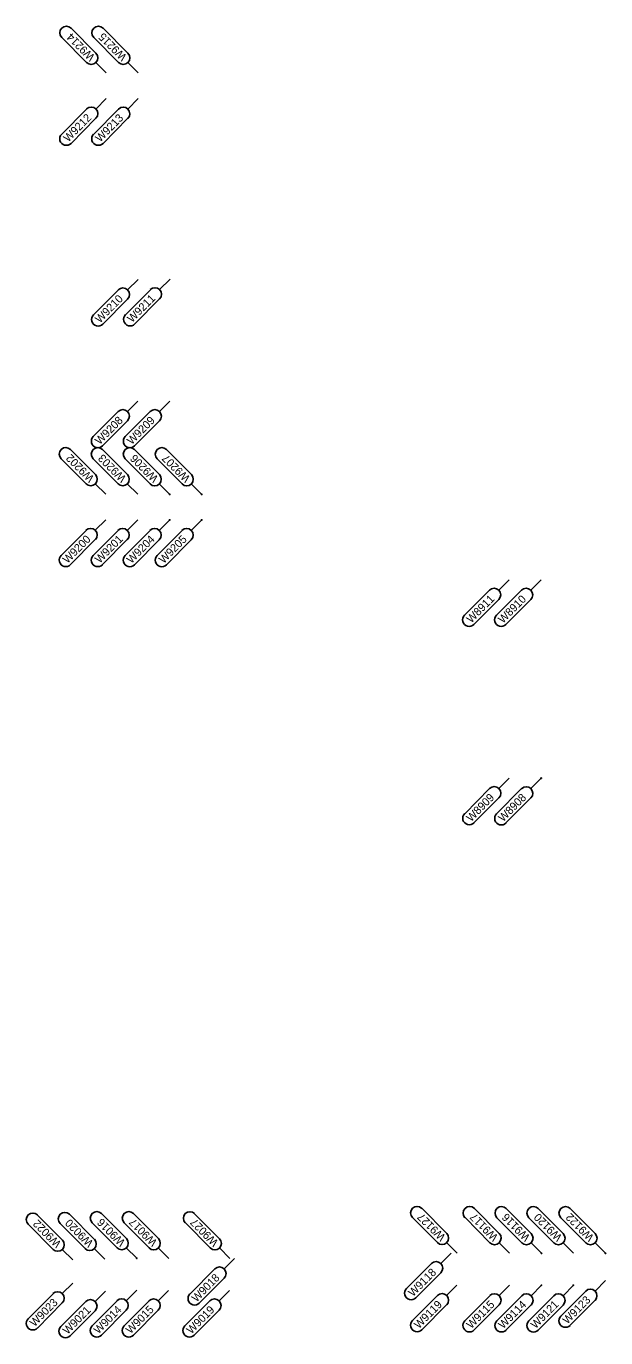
# Model space of a CAD drawing. Extents: x 12479652 to 12487250, y 9842710 to 9846560.
# Drawn here: x 12483659.7 to 12483750.3, y 9843890.4 to 9844095.3 of the extents above; entities that cross this region are included whole.
import ezdxf

# ---------------------------------------------------------------- set-up
doc = ezdxf.new("R2010")
doc.units = 0
for name, color, linetype in [('_CIVIL_CONSTRUCTION', 7, 'Continuous'), ('Default', 7, 'Continuous'), ('TextAlignmentLrg', 7, 'Continuous')]:
    doc.layers.add(name, color=color, linetype=linetype)

msp = doc.modelspace()

# ---------------------------------------------------------------- linework, layer by layer
at = {"layer": '_CIVIL_CONSTRUCTION'}
for p, q in [((12483735.18, 9844008.84), (12483733.56, 9844007.21)), ((12483740.18, 9844008.83), (12483738.56, 9844007.2)), ((12483728.22, 9844003.29), (12483732.11, 9844007.2)), ((12483733.22, 9844003.28), (12483737.11, 9844007.2)), ((12483733.57, 9844005.76), (12483729.68, 9844001.85)), ((12483738.57, 9844005.75), (12483734.68, 9844001.84)), ((12483735.2, 9843977.84), (12483733.58, 9843976.21)), ((12483740.2, 9843977.83), (12483738.58, 9843976.2)), ((12483728.24, 9843972.29), (12483732.13, 9843976.2)), ((12483733.24, 9843972.28), (12483737.13, 9843976.2)), ((12483733.58, 9843974.76), (12483729.69, 9843970.84)), ((12483738.58, 9843974.75), (12483734.69, 9843970.84))]:
    msp.add_line(p, q, dxfattribs=at)
for centre, start, end in [((12483732.84, 9844006.48), 315.1702, 135.1702), ((12483737.84, 9844006.47), 315.1702, 135.1702), ((12483728.95, 9844002.57), 135.1702, 315.1702), ((12483733.95, 9844002.56), 135.1702, 315.1702), ((12483732.86, 9843975.48), 315.1702, 135.1702), ((12483737.86, 9843975.47), 315.1702, 135.1702), ((12483728.97, 9843971.57), 135.1702, 315.1702), ((12483733.97, 9843971.56), 135.1702, 315.1702)]:
    msp.add_arc(centre, 1.03, start, end, dxfattribs=at)
at = {"layer": 'Default'}
for p, q in [((12483670.61, 9844091.09), (12483666.72, 9844095)), ((12483675.61, 9844091.08), (12483671.72, 9844094.99)), ((12483665.27, 9844093.56), (12483669.16, 9844089.64)), ((12483670.27, 9844093.55), (12483674.16, 9844089.63)), ((12483672.23, 9844088.01), (12483670.61, 9844089.64)), ((12483677.23, 9844088), (12483675.61, 9844089.63)), ((12483665.26, 9844078.46), (12483669.15, 9844082.37)), ((12483670.26, 9844078.45), (12483674.15, 9844082.36)), ((12483672.23, 9844084.01), (12483670.6, 9844082.37)), ((12483677.23, 9844084), (12483675.6, 9844082.37)), ((12483670.61, 9844080.92), (12483666.72, 9844077.01)), ((12483675.61, 9844080.92), (12483671.72, 9844077)), ((12483677.19, 9844055.75), (12483675.57, 9844054.12)), ((12483682.19, 9844055.79), (12483680.57, 9844054.16)), ((12483670.23, 9844050.2), (12483674.12, 9844054.12)), ((12483675.23, 9844050.24), (12483679.12, 9844054.15)), ((12483675.57, 9844052.67), (12483671.68, 9844048.76)), ((12483680.57, 9844052.71), (12483676.68, 9844048.79)), ((12483677.16, 9844036.75), (12483675.54, 9844035.12)), ((12483682.16, 9844036.74), (12483680.54, 9844035.11)), ((12483670.2, 9844031.2), (12483674.09, 9844035.12)), ((12483675.55, 9844033.67), (12483671.66, 9844029.76)), ((12483675.2, 9844031.19), (12483679.09, 9844035.11)), ((12483680.55, 9844033.66), (12483676.66, 9844029.75)), ((12483670.53, 9844025.27), (12483666.64, 9844029.18)), ((12483675.53, 9844025.26), (12483671.64, 9844029.18)), ((12483680.53, 9844025.26), (12483676.64, 9844029.17)), ((12483685.53, 9844025.25), (12483681.64, 9844029.16)), ((12483665.18, 9844027.74), (12483669.07, 9844023.82)), ((12483670.18, 9844027.73), (12483674.07, 9844023.82)), ((12483675.18, 9844027.72), (12483679.07, 9844023.81)), ((12483680.18, 9844027.72), (12483684.07, 9844023.8)), ((12483672.14, 9844022.19), (12483670.52, 9844023.82)), ((12483677.14, 9844022.18), (12483675.52, 9844023.81)), ((12483682.14, 9844022.17), (12483680.52, 9844023.81)), ((12483687.14, 9844022.17), (12483685.52, 9844023.8)), ((12483672.14, 9844018.19), (12483670.52, 9844016.56)), ((12483677.14, 9844018.18), (12483675.52, 9844016.55)), ((12483682.14, 9844018.17), (12483680.52, 9844016.54)), ((12483687.14, 9844018.17), (12483685.52, 9844016.54)), ((12483665.18, 9844012.64), (12483669.07, 9844016.55)), ((12483670.52, 9844015.11), (12483666.63, 9844011.19)), ((12483670.18, 9844012.63), (12483674.07, 9844016.55)), ((12483675.52, 9844015.1), (12483671.63, 9844011.19)), ((12483675.18, 9844012.63), (12483679.07, 9844016.54)), ((12483680.52, 9844015.09), (12483676.63, 9844011.18)), ((12483680.18, 9844012.62), (12483684.07, 9844016.53)), ((12483685.52, 9844015.09), (12483681.63, 9844011.17)), ((12483725.43, 9843906.73), (12483721.54, 9843910.64)), ((12483733.64, 9843906.71), (12483729.75, 9843910.63)), ((12483738.63, 9843906.71), (12483734.74, 9843910.62)), ((12483743.63, 9843906.7), (12483739.74, 9843910.61)), ((12483748.63, 9843906.69), (12483744.74, 9843910.6)), ((12483660.02, 9843908.14), (12483663.91, 9843904.23)), ((12483665.37, 9843905.68), (12483661.48, 9843909.59)), ((12483665.02, 9843908.26), (12483668.91, 9843904.35)), ((12483670.37, 9843905.79), (12483666.48, 9843909.71)), ((12483670.02, 9843908.38), (12483673.91, 9843904.47)), ((12483675.37, 9843905.91), (12483671.48, 9843909.83)), ((12483675.02, 9843908.37), (12483678.91, 9843904.46)), ((12483680.37, 9843905.91), (12483676.48, 9843909.82)), ((12483684.59, 9843908.36), (12483688.48, 9843904.44)), ((12483689.93, 9843905.89), (12483686.04, 9843909.8)), ((12483720.09, 9843909.19), (12483723.98, 9843905.28)), ((12483728.3, 9843909.18), (12483732.19, 9843905.27)), ((12483733.28, 9843909.17), (12483737.17, 9843905.26)), ((12483738.28, 9843909.16), (12483742.17, 9843905.25)), ((12483743.28, 9843909.16), (12483747.17, 9843905.24)), ((12483666.99, 9843902.59), (12483665.36, 9843904.22)), ((12483671.99, 9843902.71), (12483670.36, 9843904.34)), ((12483676.99, 9843902.83), (12483675.36, 9843904.46)), ((12483681.99, 9843902.82), (12483680.36, 9843904.45)), ((12483691.55, 9843902.81), (12483689.93, 9843904.44)), ((12483727.05, 9843903.64), (12483725.43, 9843905.27)), ((12483735.26, 9843903.63), (12483733.64, 9843905.26)), ((12483740.24, 9843903.62), (12483738.62, 9843905.25)), ((12483745.24, 9843903.62), (12483743.62, 9843905.25)), ((12483750.24, 9843903.61), (12483748.62, 9843905.24)), ((12483692.28, 9843902.81), (12483690.66, 9843901.18)), ((12483719.17, 9843898.1), (12483723.06, 9843902.01)), ((12483726.13, 9843903.64), (12483724.51, 9843902.01)), ((12483685.32, 9843897.26), (12483689.21, 9843901.17)), ((12483724.51, 9843900.56), (12483720.62, 9843896.65)), ((12483666.98, 9843898.94), (12483665.36, 9843897.31)), ((12483690.66, 9843899.73), (12483686.77, 9843895.81)), ((12483727.04, 9843898.64), (12483725.42, 9843897.01)), ((12483735.23, 9843898.63), (12483733.61, 9843897)), ((12483740.23, 9843898.62), (12483738.61, 9843896.99)), ((12483745.23, 9843898.62), (12483743.61, 9843896.98)), ((12483750.24, 9843899.35), (12483748.61, 9843897.72)), ((12483660.02, 9843893.39), (12483663.91, 9843897.3)), ((12483665.36, 9843895.86), (12483661.47, 9843891.94)), ((12483665.14, 9843892.17), (12483669.03, 9843896.08)), ((12483670.02, 9843892.28), (12483673.91, 9843896.2)), ((12483672.1, 9843897.71), (12483670.48, 9843896.08)), ((12483675.02, 9843892.27), (12483678.91, 9843896.19)), ((12483676.98, 9843897.83), (12483675.36, 9843896.2)), ((12483681.98, 9843897.82), (12483680.36, 9843896.19)), ((12483684.52, 9843892.26), (12483688.41, 9843896.17)), ((12483691.49, 9843897.81), (12483689.86, 9843896.18)), ((12483720.08, 9843893.09), (12483723.97, 9843897.01)), ((12483728.27, 9843893.08), (12483732.16, 9843896.99)), ((12483733.27, 9843893.07), (12483737.16, 9843896.99)), ((12483738.27, 9843893.07), (12483742.16, 9843896.98)), ((12483743.27, 9843893.8), (12483747.16, 9843897.72)), ((12483748.62, 9843896.27), (12483744.73, 9843892.36)), ((12483670.49, 9843894.63), (12483666.6, 9843890.72)), ((12483675.36, 9843894.75), (12483671.47, 9843890.84)), ((12483680.36, 9843894.74), (12483676.47, 9843890.83)), ((12483689.87, 9843894.73), (12483685.98, 9843890.81)), ((12483725.42, 9843895.56), (12483721.53, 9843891.65)), ((12483733.62, 9843895.55), (12483729.73, 9843891.64)), ((12483738.62, 9843895.54), (12483734.73, 9843891.63)), ((12483743.62, 9843895.53), (12483739.73, 9843891.62))]:
    msp.add_line(p, q, dxfattribs=at)
for centre, start, end in [((12483666, 9844094.28), 44.8253, 224.8253), ((12483671, 9844094.27), 44.8253, 224.8253), ((12483669.89, 9844090.37), 224.8253, 44.8253), ((12483674.89, 9844090.36), 224.8253, 44.8253), ((12483669.88, 9844081.65), 315.1702, 135.1702), ((12483674.88, 9844081.64), 315.1702, 135.1702), ((12483665.99, 9844077.73), 135.1702, 315.1702), ((12483670.99, 9844077.73), 135.1702, 315.1702), ((12483674.84, 9844053.39), 315.1702, 135.1702), ((12483679.84, 9844053.43), 315.1702, 135.1702), ((12483670.95, 9844049.48), 135.1702, 315.1702), ((12483675.95, 9844049.52), 135.1702, 315.1702), ((12483674.82, 9844034.39), 315.1702, 135.1702), ((12483679.82, 9844034.38), 315.1702, 135.1702), ((12483670.93, 9844030.48), 135.1702, 315.1702), ((12483675.93, 9844030.47), 135.1702, 315.1702), ((12483665.91, 9844028.46), 44.8253, 224.8253), ((12483670.91, 9844028.45), 44.8253, 224.8253), ((12483675.91, 9844028.45), 44.8253, 224.8253), ((12483680.91, 9844028.44), 44.8253, 224.8253), ((12483669.8, 9844024.55), 224.8253, 44.8253), ((12483674.8, 9844024.54), 224.8253, 44.8253), ((12483679.8, 9844024.53), 224.8253, 44.8253), ((12483684.8, 9844024.53), 224.8253, 44.8253), ((12483669.79, 9844015.83), 315.1702, 135.1702), ((12483674.79, 9844015.82), 315.1702, 135.1702), ((12483679.79, 9844015.82), 315.1702, 135.1702), ((12483684.79, 9844015.81), 315.1702, 135.1702), ((12483665.9, 9844011.92), 135.1702, 315.1702), ((12483670.9, 9844011.91), 135.1702, 315.1702), ((12483675.9, 9844011.9), 135.1702, 315.1702), ((12483680.9, 9844011.9), 135.1702, 315.1702), ((12483720.81, 9843909.91), 44.8253, 224.8253), ((12483729.02, 9843909.9), 44.8253, 224.8253), ((12483734.01, 9843909.89), 44.8253, 224.8253), ((12483739.01, 9843909.89), 44.8253, 224.8253), ((12483744.01, 9843909.88), 44.8253, 224.8253), ((12483660.75, 9843908.87), 44.8253, 224.8253), ((12483665.75, 9843908.98), 44.8253, 224.8253), ((12483670.75, 9843909.1), 44.8253, 224.8253), ((12483675.75, 9843909.1), 44.8253, 224.8253), ((12483685.31, 9843909.08), 44.8253, 224.8253), ((12483724.7, 9843906), 224.8253, 44.8253), ((12483732.91, 9843905.99), 224.8253, 44.8253), ((12483737.9, 9843905.98), 224.8253, 44.8253), ((12483742.9, 9843905.97), 224.8253, 44.8253), ((12483747.9, 9843905.97), 224.8253, 44.8253), ((12483664.64, 9843904.95), 224.8253, 44.8253), ((12483669.64, 9843905.07), 224.8253, 44.8253), ((12483674.64, 9843905.19), 224.8253, 44.8253), ((12483679.64, 9843905.18), 224.8253, 44.8253), ((12483689.2, 9843905.17), 224.8253, 44.8253), ((12483723.78, 9843901.29), 315.1702, 135.1702), ((12483689.93, 9843900.45), 315.1702, 135.1702), ((12483719.89, 9843897.37), 135.1702, 315.1702), ((12483747.89, 9843896.99), 315.1702, 135.1702), ((12483664.63, 9843896.58), 315.1702, 135.1702), ((12483669.76, 9843895.35), 315.1702, 135.1702), ((12483674.63, 9843895.47), 315.1702, 135.1702), ((12483679.63, 9843895.46), 315.1702, 135.1702), ((12483686.04, 9843896.54), 135.1702, 315.1702), ((12483689.14, 9843895.45), 315.1702, 135.1702), ((12483724.7, 9843896.28), 315.1702, 135.1702), ((12483732.89, 9843896.27), 315.1702, 135.1702), ((12483737.89, 9843896.26), 315.1702, 135.1702), ((12483742.89, 9843896.26), 315.1702, 135.1702), ((12483744, 9843893.08), 135.1702, 315.1702), ((12483660.75, 9843892.67), 135.1702, 315.1702), ((12483665.87, 9843891.44), 135.1702, 315.1702), ((12483670.74, 9843891.56), 135.1702, 315.1702), ((12483675.74, 9843891.55), 135.1702, 315.1702), ((12483685.25, 9843891.54), 135.1702, 315.1702), ((12483720.81, 9843892.37), 135.1702, 315.1702), ((12483729, 9843892.36), 135.1702, 315.1702), ((12483734, 9843892.35), 135.1702, 315.1702), ((12483739, 9843892.34), 135.1702, 315.1702)]:
    msp.add_arc(centre, 1.03, start, end, dxfattribs=at)
at = {"layer": 'TextAlignmentLrg'}
for centre in [(12483682.14, 9844022.17), (12483687.14, 9844022.17), (12483682.14, 9844018.17), (12483687.14, 9844018.17), (12483740.2, 9843977.83), (12483676.99, 9843902.83), (12483740.24, 9843903.62), (12483750.24, 9843903.61), (12483740.23, 9843898.62), (12483745.23, 9843898.62)]:
    msp.add_circle(centre, 0.05, dxfattribs=at)

# ---------------------------------------------------------------- texts
at = {"layer": '_CIVIL_CONSTRUCTION'}
for s, p in [('W8911', (12483729.26, 9844001.98)), ('W8910', (12483734.22, 9844001.93)), ('W8909', (12483729.24, 9843970.94)), ('W8908', (12483734.24, 9843970.93))]:
    msp.add_text(s, height=1.25, rotation=45.1702, dxfattribs=at).set_placement(p)
at = {"layer": 'Default'}
for s, rotation, p in [('W9214', 134.8253, (12483670.54, 9844090.6)), ('W9215', 134.8253, (12483675.52, 9844090.62)), ('W9212', 45.1702, (12483666.28, 9844077.13)), ('W9213', 45.1702, (12483671.27, 9844077.11)), ('W9210', 45.1702, (12483671.22, 9844048.85)), ('W9211', 45.1702, (12483676.26, 9844048.92)), ('W9208', 45.1702, (12483671.2, 9844029.85)), ('W9209', 45.1702, (12483676.2, 9844029.85)), ('W9202', 134.8253, (12483670.43, 9844024.81)), ('W9203', 134.8253, (12483675.44, 9844024.79)), ('W9206', 134.8253, (12483680.45, 9844024.78)), ('W9207', 134.8253, (12483685.44, 9844024.78)), ('W9200', 45.1702, (12483666.17, 9844011.29)), ('W9201', 45.1702, (12483671.21, 9844011.32)), ('W9204', 45.1702, (12483676.17, 9844011.27)), ('W9205', 45.1702, (12483681.19, 9844011.28)), ('W9022', 134.8253, (12483665.27, 9843905.22)), ('W9020', 134.8253, (12483670.29, 9843905.32)), ('W9016', 134.8253, (12483675.29, 9843905.43)), ('W9017', 134.8253, (12483680.28, 9843905.44)), ('W9027', 134.8253, (12483689.84, 9843905.42)), ('W9127', 134.8253, (12483725.34, 9843906.26)), ('W9117', 134.8253, (12483733.55, 9843906.25)), ('W9116', 134.8253, (12483738.55, 9843906.22)), ('W9120', 134.8253, (12483743.55, 9843906.22)), ('W9122', 134.8253, (12483748.53, 9843906.23)), ('W9018', 45.1702, (12483686.32, 9843895.91)), ('W9118', 45.1702, (12483720.17, 9843896.75)), ('W9023', 45.1702, (12483661.02, 9843892.05)), ('W9119', 45.1702, (12483721.08, 9843891.74)), ('W9115', 45.1702, (12483729.28, 9843891.74)), ('W9114', 45.1702, (12483734.26, 9843891.72)), ('W9121', 45.1702, (12483739.31, 9843891.75)), ('W9123', 45.1702, (12483744.28, 9843892.46)), ('W9021', 45.1702, (12483666.18, 9843890.85)), ('W9014', 45.1702, (12483671.01, 9843890.92)), ('W9015', 45.1702, (12483676.03, 9843890.94)), ('W9019', 45.1702, (12483685.52, 9843890.91))]:
    msp.add_text(s, height=1.25, rotation=rotation, dxfattribs=at).set_placement(p)

doc.saveas('drawing.dxf')
